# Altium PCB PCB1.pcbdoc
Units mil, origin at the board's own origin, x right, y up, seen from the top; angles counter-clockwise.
Board outline 1815 x 1125 mil, 2 copper layers (Top Layer, Bottom Layer); 37 components, 25 nets, 96 pads, 7 vias.
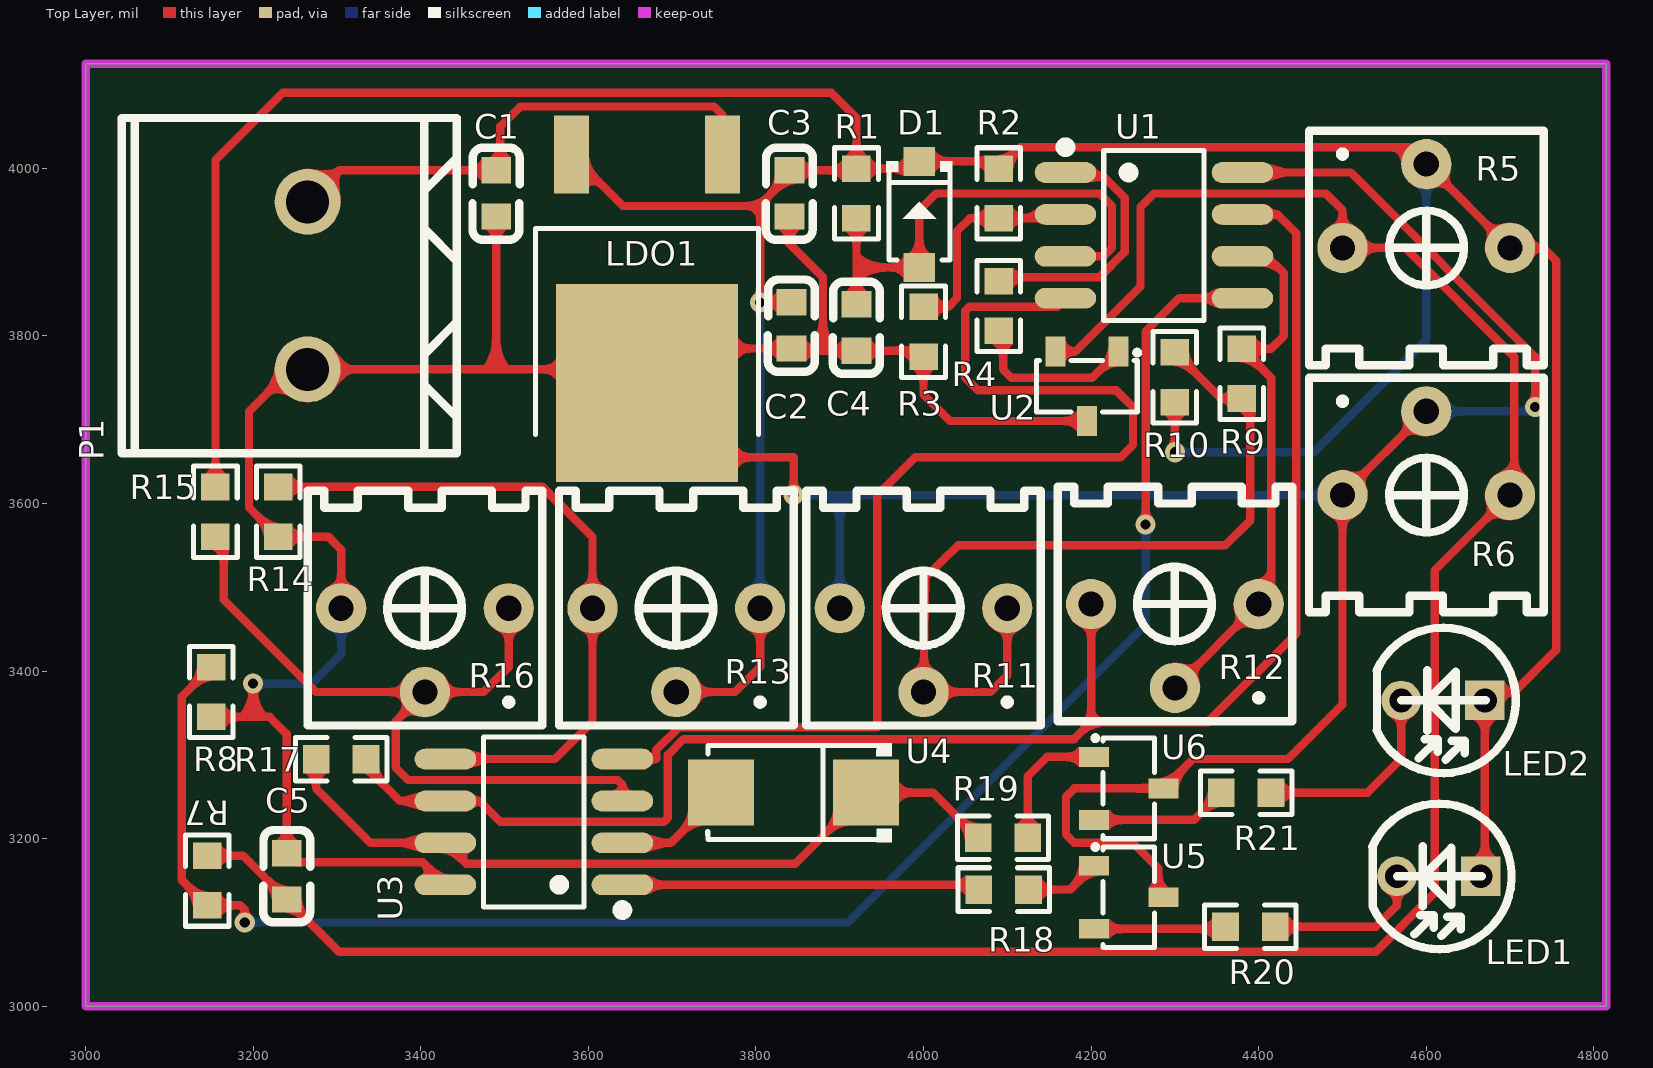
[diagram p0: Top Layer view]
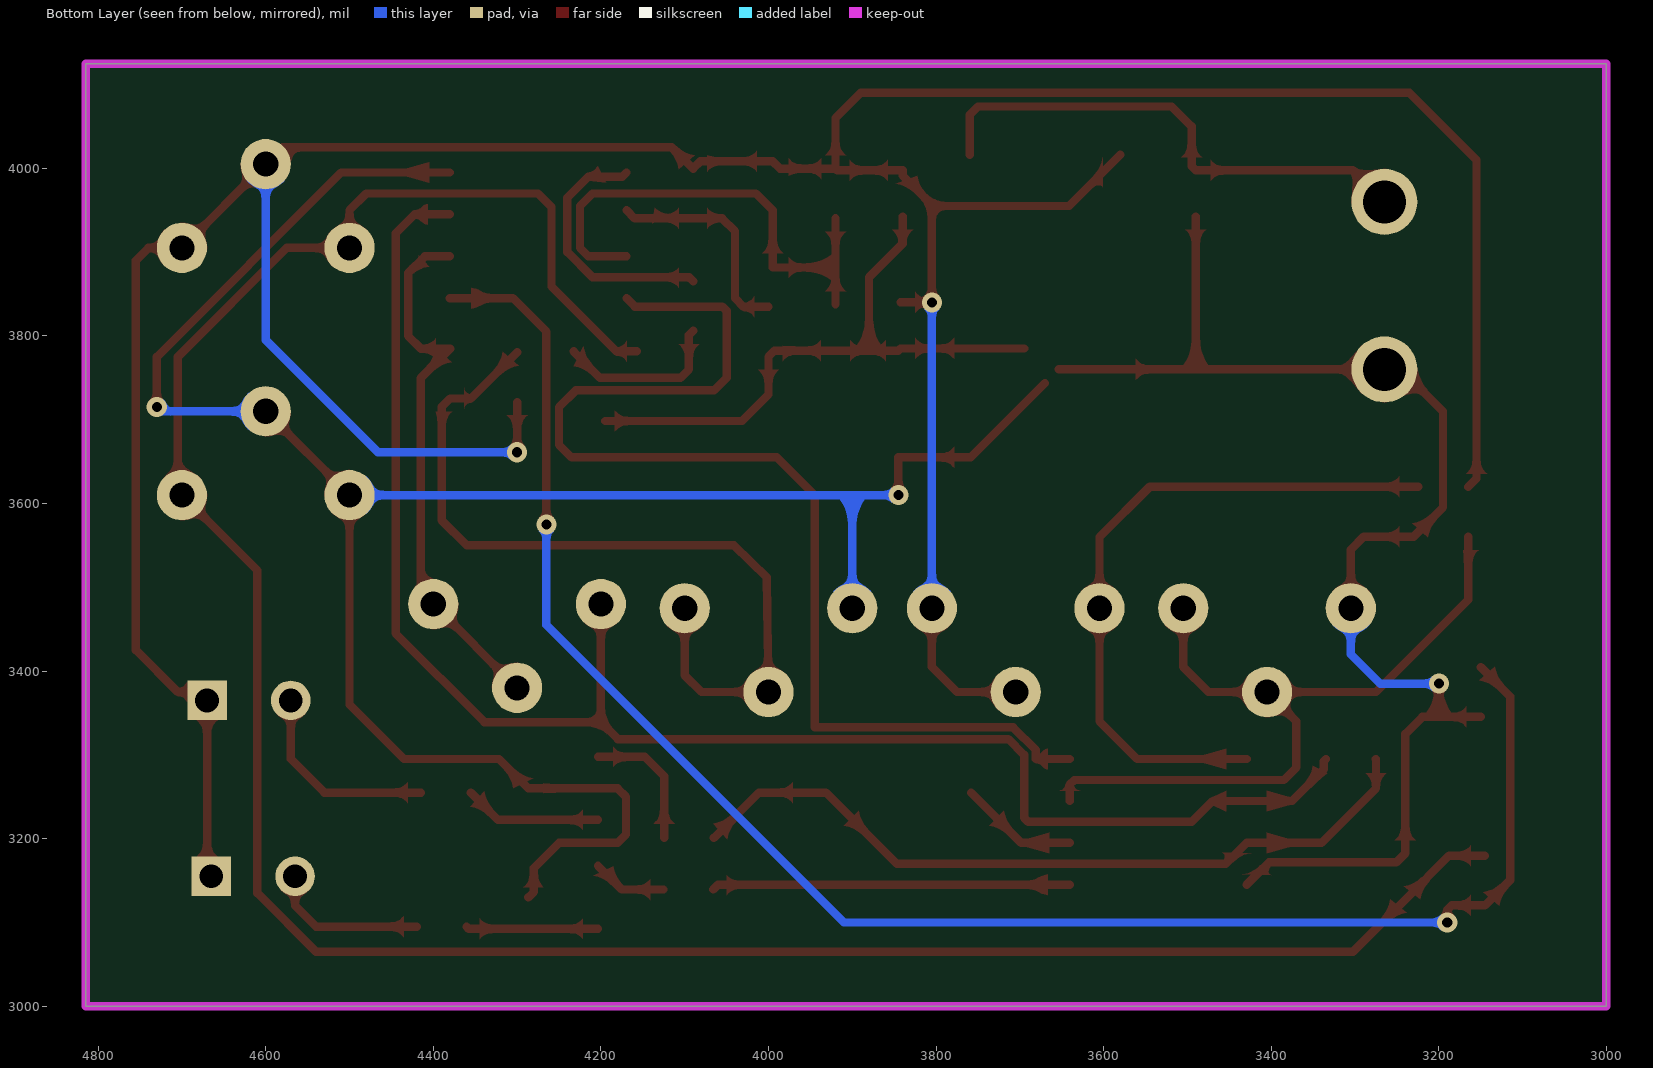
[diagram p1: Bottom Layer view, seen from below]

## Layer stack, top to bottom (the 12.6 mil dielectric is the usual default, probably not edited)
Top Layer: signal copper (thickness not stored)
Dielectric: dielectric 12.6, FR-4, Dk 4.8
Bottom Layer: signal copper (thickness not stored)

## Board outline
3000,3000 4815,3000 4815,4125 3000,4125

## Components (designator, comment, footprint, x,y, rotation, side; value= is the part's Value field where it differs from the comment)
C1 "CAP_0603" C0603 3490,3970 r90 top
C2 "CAP_0603" C0603 3842.44,3812.56 r90 top
C3 "CAP_0603" C0603 3840,3970 r90 top
C4 "CAP_0603" C0603 3920,3810 r90 top
C5 "CAP_0603" C0603 3240,3155 r270 top
D1 "1N4148W_C7420318" SOD-123_L2.7-W1.6-LS3.7-FD 3995,3945 r90 top
LDO1 "CJ7805 3%" TO-252-2_L6.6-W6.1-P4.58-LS10.1-BR-CW 3670,3880 r90 top
LED1 "PD204-6B" LED-TH_BD3.1-P2.54-FD 4615,3155 r180 top
LED2 "PD204-6B" LED-TH_BD3.1-P2.54-FD 4620,3365 r180 top
P1 "WJ500V-5.08-2P" CONN-TH_2P-P5.00_WJ500V-5.08-2P 3265,3860 r90 top
R1 "0603WAF1002T5E" R0603 3920,3970 r90 top
R2 "Res_0603" R0603 4090,3970 r90 top
R3 "Res_0603" R0603 4000,3805 r90 top
R4 "Res_0603" R0603 4090,3835.68 r270 top
R5 "3362P-1-103" RES-ADJ-TH_3362P 4600,3955 r0 top
R6 "3362P-1-103" RES-ADJ-TH_3362P 4600,3660 r0 top
R7 "Res_0603" R0603 3145,3150 r90 top
R8 "Res_0603" R0603 3150,3375 r90 top
R9 "Res_0603" R0603 4380,3755 r90 top
R10 "Res_0603" R0603 4300,3750.68 r270 top
R11 "3362P-1-103" RES-ADJ-TH_3362P 4000,3425 r180 top
R12 "3362P-1-103" RES-ADJ-TH_3362P 4300,3430 r180 top
R13 "3362P-1-103" RES-ADJ-TH_3362P 3705,3425 r180 top
R14 "Res_0603" R0603 3230,3590 r90 top
R15 "Res_0603" R0603 3155,3590 r90 top
R16 "3362P-1-103" RES-ADJ-TH_3362P 3405,3425 r180 top
R17 "Res_0603" R0603 3305,3295 r0 top
R18 "Res_0603" R0603 4095.59,3139.27 r180 top
R19 "Res_0603" R0603 4094.91,3201.03 r0 top
R20 "Res_0603" R0603 4390,3095 r180 top
R21 "Res_0603" R0603 4385,3255 r180 top
U1 "LM358_C5252902" SOP-8_L4.9-W3.9-P1.27-LS6.0-BL 4275,3920 r270 top
U2 "S9012_C5204710" SOT-23-3_L2.9-W1.4-P1.90-LS2.6-BR 4195,3740 r90 top
U3 "LM358_C5252902" SOP-8_L4.9-W3.9-P1.27-LS6.0-BL 3535,3220 r90 top
U4 "1N4007" SMA_L4.3-W2.6-LS5.1-RD 3845,3255 r180 top
U5 "S9012_C5204710" SOT-23-3_L2.9-W1.4-P1.90-LS2.6-BR 4245,3130 r180 top
U6 "S9012_C5204710" SOT-23-3_L2.9-W1.4-P1.90-LS2.6-BR 4245,3260 r180 top

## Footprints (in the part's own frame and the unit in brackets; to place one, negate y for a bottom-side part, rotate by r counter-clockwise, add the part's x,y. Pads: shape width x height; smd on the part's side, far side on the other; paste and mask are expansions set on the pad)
C0603 [mm]
  rect 0.8x0.9 smd: 1(-0.7,0) 2(0.7,0)
  silkscreen extent -1.41,-0.71 1.39,0.72
CONN-TH_2P-P5.00_WJ500V-5.08-2P [mm]
  round 2 hole 1.3: 1(-2.54,0) 2(2.54,0)
  silkscreen extent -5.08,-4.52 5.08,5.64
LED-TH_BD3.1-P2.54-FD [mm]
  rect 1.2x1.2 hole 0.72: 1(-1.27,0)
  round 1.2 hole 0.72: 2(1.27,0)
  silkscreen extent -2.2,-2.21 2.02,2.21
R0603 [mil]
  rect 31.75x34.02 smd: 1(-29.66,0) 2(29.66,0)
  silkscreen extent -55,-26 55,26
RES-ADJ-TH_3362P [mil]
  round 60 hole 30: 1(-100,-50) 2(0,50) 3(100,-50)
  silkscreen extent -140,-190 140,90
SMA_L4.3-W2.6-LS5.1-RD [mm]
  rect 2x2 smd: 1(-2.2,0) 2(2.2,0)
  silkscreen extent -2.98,-1.5 2.6,1.5
SOD-123_L2.7-W1.6-LS3.7-FD [mm]
  rect 0.88x0.96 smd: 1(-1.61,0) 2(1.61,0)
  silkscreen extent -1.38,-1 1.6,1
SOP-8_L4.9-W3.9-P1.27-LS6.0-BL [mm]
  oval 0.63x1.865 smd: 1(-1.905,-2.682) 2(-0.635,-2.682) 3(0.635,-2.682) 4(1.905,-2.682) 5(1.905,2.682) 6(0.635,2.682) 7(-0.635,2.682) 8(-1.905,2.682)
  silkscreen extent -2.82,-2.83 2.58,1.52
SOT-23-3_L2.9-W1.4-P1.90-LS2.6-BR [mm]
  rect 0.91x0.6 smd: 1(1.055,-0.955) 2(1.055,0.955) 3(-1.055,0)
  silkscreen extent -0.78,-1.6 1.09,1.53
TO-252-2_L6.6-W6.1-P4.58-LS10.1-BR-CW [mil]
  rect 93.07x41.89 smd: 1(136.3,-90) 3(136.3,90)
  rect 236.37x217.01 smd: 2(-136.3,0)
  silkscreen extent -198,-133 48,133

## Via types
v1: diameter 24.02, hole 12.01, Top Layer to Bottom Layer, 7 vias

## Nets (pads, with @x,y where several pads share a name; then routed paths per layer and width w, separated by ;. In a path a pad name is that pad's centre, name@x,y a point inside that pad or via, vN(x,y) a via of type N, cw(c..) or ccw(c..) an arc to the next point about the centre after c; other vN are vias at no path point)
$1N1076: C1.2 LDO1.1 P1.2 | length 621.6
  Top Layer w10: P1.2 3302.56,3997.56 C1.2 3495,4002.56 3495,4050 3518.83,4073.83 3750,4073.83 3760,4063.83 LDO1.1
$1N1870: C4.2 D1.1 R1.1 U1.3 | length 600.8
  Top Layer w10: C4.2 3920,3880.72 ; R1.1 3920,3880.72 ; U1.3 4215,3895 4225,3905 4225,3955 4210,3970 4015,3970 3995,3950 D1.1 3920.89,3881.61 3920,3880.72
$1N2082: R2.1 R3.2 U1.2 | length 264
  Top Layer w10: R3.2 4029.66,3834.66 4040,3845 4040,3925 4055.34,3940.34 R2.1 4159.73,3940.34 U1.2@4169.39,3950
$1N2247: R4.1 U1.1 | length 312.4
  Top Layer w10: R4.1 4094.66,3870 4210,3870 4240,3900 4240,3965 4215,3990 4174.39,3990 U1.1
$1N2341: R4.2 U2.1 | length 202.9
  Top Layer w10: R4.2 4095,3801.02 4095,3760 4105,3750 4201.06,3750 U2.1
$1N2823: C5.2 R5.1 R6.3 R7.2 U2.2 | length 3009.3
  Top Layer w10: R7.2 3187.78,3179.66 C5.2 3302.44,3065 4540,3065 4610,3135 4610,3520 R6.3 4705,3615 4705,3775 4575,3905 R5.1 4500,3950 4480,3970 4275,3970 4258.98,3953.98 4258.98,3858.98 4181.54,3781.54 U2.2
$1N2886: R7.1 R8.2 U1.5 | length 2077.7
  Top Layer w10: R8.2 3115,3369.66 3115,3150.34 R7.1 3184.66,3120.34 3190,3115 v1(3190,3100) ; v1(4265,3575) 4265,3805 4305,3845 U1.5
  Bottom Layer w10: v1(3190,3100) 3910,3100 4265,3455 v1(4265,3575)
$1N3156: R9.1 R10.1 R11.1 R11.2 | length 993.4
  Top Layer w10: R11.1 4100,3395 4080,3375 R11.2 4001.93,3511.87 4041.14,3550 4360,3550 4390,3580 4390,3715.34 R9.1 4355,3725.34 R10.1
$1N3303: R9.2 R12.1 R12.2 U1.6 | length 663.9
  Top Layer w10: R12.2 R12.1 ; U1.6 4410,3895 4430,3875 4430,3800 4414.66,3784.66 R9.2 4415,3749.66 4415,3505 R12.1@4407.69,3497.69 ; R12.1@4407.69,3497.69 4405.38,3500 4400,3500 4400.26,3499.74 4400.26,3490.26 R12.1@4407.69,3497.69
$1N4357: U3.2 U4.2 | length 142.6
  Top Layer w10: U3.2 3698.39,3195 U4.2
$1N4404: R15.1 R16.1 R16.2 U3.3 | length 946.4
  Top Layer w10: R15.1@3165,3560.34 3165,3485 3275,3375 R16.2 ; R16.1 3505,3405 3475,3375 R16.2 ; U3.3 3640.61,3264.39 3635,3270 3385,3270 3370,3285 3370,3340 R16.2
$1N4441: R13.3 R14.2 U3.5 | length 819.4
  Top Layer w10: R14.2@3224.66,3620 3545,3620 3605,3560 R13.3 3605,3340 3560,3295 U3.5
$1N4449: R12.3 R17.2 U1.7 U3.6 | length 1986.3
  Top Layer w10: R17.2 3337.33,3292.33 3337.33,3282.67 3375,3245 U3.6 3470,3245 3495,3220 3690,3220 3695,3225 3695,3300 3713.78,3318.78 4179.78,3318.78 4200,3339 ; R12.3@4200,3490 4200,3339 ; U1.7 4422.32,3945 4445,3922.32 4445,3445 4339,3339 4200,3339
$1N4581: R18.2 U3.1 | length 427.7
  Top Layer w10: U3.1 4060.2,3145 R18.2
$1N4611: R17.1 R19.1 U3.7 U4.1 | length 920.2
  Top Layer w10: R17.1 3275,3294.66 3275,3260 3340,3195 U3.7 3454.39,3170 3846.62,3170 U4.1 4011.29,3255 R19.1
$1N4719: R18.1 U5.1 | length 89.9
  Top Layer w10: R18.1 4175.13,3139.27 U5.1
$1N4722: R19.2 U6.1 | length 162
  Top Layer w10: R19.2 4124.57,3274.57 4147.6,3297.6 U6.1
$1N4773: R21.2 U6.2 | length 165.4
  Top Layer w10: U6.2 4322.74,3222.4 R21.2
$1N4777: R20.2 U5.2 | length 158
  Top Layer w10: U5.2 4357.74,3092.4 R20.2
$1N4889: LED2.2 R21.1 | length 241.9
  Top Layer w10: R21.1 4530,3255 4570,3295 LED2.2
$1N4892: LED1.2 R20.1 | length 190.7
  Top Layer w10: R20.1 4540,3095 4565,3120 LED1.2
$1N5001: C2.2 C3.2 D1.2 LDO1.3 LED1.1 LED2.1 R1.2 R2.2 R5.2 R5.3 R10.2 R13.1 R13.2 R15.2 | length 4665.4
  Top Layer w10: R15.2@3165,3619.66 3155,3629.66 3155,4010 3235,4090 3890,4090 3920,4060 R1.2 ; LDO1.3 3641.3,3955 3803.54,3955 ; R13.2 3775,3375 3805,3405 R13.1 ; C2.2 3842.32,3840 v1(3805,3840) 3805,3953.54 3803.54,3955 ; v1@4300,3670 R10.2 ; LED1.1 4670,3160 LED2.1 4680,3375 4705,3375 4755,3425 4755,3890 4740,3905 R5.3 R5.2 4580,4025 4115.34,4025 R2.2 4081.27,4008.39 D1.2 3986.27,3999.66 R1.2 ; 3803.54,3955 3840,3991.46 C3.2 3917.9,3997.56 R1.2
  Bottom Layer w10: R13.1 v1(3805,3840) ; v1(4300,3661.12) 4466.12,3661.12 4600,3795 R5.2
+9V: U1.4 U3.4 | length 1398.5
  Top Layer w10: U3.4 3680.98,3295 3680.98,3305.81 3707.97,3332.79 3945,3332.79 3945,3610 3990,3655 4235,3655 4250,3670 4250,3715 4230,3735 4065,3735 4050,3750 4050,3830 4055,3835 4159.39,3835 U1.4
GND: C1.1 C2.1 C3.1 C4.1 C5.1 LDO1.2 P1.1 R3.1 R6.1 R6.2 R8.1 R11.3 R14.1 R16.3 U1.8 U2.3 U3.8 U5.3 U6.3 | length 5032.5
  Top Layer w10: R8.1 3200,3345.34 ; v1(3200,3385) 3200,3345.34 ; R16.3 3305,3545 3289.66,3560.34 R14.1 3195,3595.34 3195,3710 3245,3760 P1.1 3490,3760 ; U3.8 3402.67,3171.72 3250.84,3171.72 C5.1 3240,3325 3219.66,3345.34 3200,3345.34 ; C1.1 3490,3760 ; LDO1.2@3653.7,3760 3490,3760 ; LDO1.2 3758.7,3655 3845,3655 v1(3845,3610) ; LDO1.2@3695,3785 C2.1 3845,3782.44 3881.17,3782.44 ; C3.1 3840,3910 3880,3870 3880,3783.61 3881.17,3782.44 ; U2.3 4031.54,3698.46 4000,3730 R3.1 3992.9,3782.44 C4.1 3881.17,3782.44 ; U5.3 4280,3136.54 4280,3165 4250,3195 4180,3195 4170,3205 4170,3250 4180,3260 U6.3 4321.54,3295 4435,3295 4500,3360 R6.1 R6.2 ; U1.8 4510,3995 4730,3775 v1(4730,3715)
  Bottom Layer w10: v1(3200,3385) 3270,3385 3305,3420 R16.3 ; v1(3845,3610) 3900.23,3610 ; R11.3 3900,3609.77 3900.23,3610 ; R6.1 3900.23,3610 ; R6.2 4725,3710 v1(4730,3715)
"": 

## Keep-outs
Board Outline Layer:
  the board outline again, w10

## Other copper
Top Layer:
  drawing of 140 lines, arcs and shapes, not listed
Bottom Layer:
  region net $1N5001: 4595,3964.16 4605,3964.16 4605.06,3965.92 4605.16,3966.99 4605.3,3967.98 4605.49,3968.9 4605.73,3969.75 4606.01,3970.54 4606.33,3971.28 4606.69,3971.96 4607.08,3972.59 4607.52,3973.18 4607.98,3973.73 4608.48,3974.26 4609.01,3974.75 4609.87,3975.45 4611.1,3976.33 4615.31,3979.04 4617.24,3980.38 4618.83,3981.61 4620.05,3982.66 4621.27,3983.84 4622.5,3985.16 4577.5,3985.16 4578.73,3983.84 4579.95,3982.66 4581.57,3981.29 4583.15,3980.09 4585.8,3978.32 4589.22,3976.12 4590.13,3975.45 4590.99,3974.75 4591.52,3974.26 4592.02,3973.73 4592.48,3973.18 4592.92,3972.59 4593.31,3971.96 4593.67,3971.28 4593.99,3970.54 4594.27,3969.75 4594.51,3968.9 4594.7,3967.98 4594.84,3966.99 4594.94,3965.92
  region net GND: 4640.84,3705 4640.84,3715 4639.08,3715.06 4638.01,3715.16 4637.02,3715.3 4636.1,3715.49 4635.25,3715.73 4634.46,3716.01 4633.72,3716.33 4633.04,3716.69 4632.41,3717.08 4631.82,3717.52 4631.27,3717.98 4630.74,3718.48 4630.25,3719.01 4629.55,3719.87 4628.67,3721.1 4625.96,3725.31 4624.62,3727.24 4623.39,3728.83 4622.34,3730.05 4621.16,3731.27 4619.84,3732.5 4619.84,3687.5 4621.16,3688.73 4622.34,3689.95 4623.71,3691.57 4624.91,3693.15 4626.68,3695.8 4628.88,3699.22 4629.55,3700.13 4630.25,3700.99 4630.74,3701.52 4631.27,3702.02 4631.82,3702.48 4632.41,3702.92 4633.04,3703.31 4633.72,3703.67 4634.46,3703.99 4635.25,3704.27 4636.1,3704.51 4637.02,3704.7 4638.01,3704.84 4639.08,3704.94
  region net GND: 4459.16,3615 4459.16,3605 4460.92,3604.94 4461.99,3604.84 4462.98,3604.7 4463.9,3604.51 4464.75,3604.27 4465.54,3603.99 4466.28,3603.67 4466.96,3603.31 4467.59,3602.92 4468.18,3602.48 4468.73,3602.02 4469.26,3601.52 4469.75,3600.99 4470.45,3600.13 4471.33,3598.9 4474.04,3594.69 4475.38,3592.76 4476.61,3591.17 4477.66,3589.95 4478.84,3588.73 4480.16,3587.5 4480.16,3632.5 4478.84,3631.27 4477.66,3630.05 4476.29,3628.43 4475.09,3626.85 4473.32,3624.2 4471.12,3620.78 4470.45,3619.87 4469.75,3619.01 4469.26,3618.48 4468.73,3617.98 4468.18,3617.52 4467.59,3617.08 4466.96,3616.69 4466.28,3616.33 4465.54,3616.01 4464.75,3615.73 4463.9,3615.49 4462.98,3615.3 4461.99,3615.16 4460.92,3615.06
  region net GND: 3905,3515.84 3895,3515.84 3894.94,3514.08 3894.84,3513.01 3894.7,3512.02 3894.51,3511.1 3894.27,3510.25 3893.99,3509.46 3893.67,3508.72 3893.31,3508.04 3892.92,3507.41 3892.48,3506.82 3892.02,3506.27 3891.52,3505.74 3890.99,3505.25 3890.13,3504.55 3888.9,3503.67 3884.69,3500.96 3882.76,3499.62 3881.17,3498.39 3879.95,3497.34 3878.73,3496.16 3877.5,3494.84 3922.5,3494.84 3921.27,3496.16 3920.05,3497.34 3918.43,3498.71 3916.85,3499.91 3914.2,3501.68 3910.78,3503.88 3909.87,3504.55 3909.01,3505.25 3908.48,3505.74 3907.98,3506.27 3907.52,3506.82 3907.08,3507.41 3906.69,3508.04 3906.33,3508.72 3906.01,3509.46 3905.73,3510.25 3905.49,3511.1 3905.3,3512.02 3905.16,3513.01 3905.06,3514.08
  region net $1N5001: 3810,3515.84 3800,3515.84 3799.94,3514.08 3799.84,3513.01 3799.7,3512.02 3799.51,3511.1 3799.27,3510.25 3798.99,3509.46 3798.67,3508.72 3798.31,3508.04 3797.92,3507.41 3797.48,3506.82 3797.02,3506.27 3796.52,3505.74 3795.99,3505.25 3795.13,3504.55 3793.9,3503.67 3789.69,3500.96 3787.76,3499.62 3786.17,3498.39 3784.95,3497.34 3783.73,3496.16 3782.5,3494.84 3827.5,3494.84 3826.27,3496.16 3825.05,3497.34 3823.43,3498.71 3821.85,3499.91 3819.2,3501.68 3815.78,3503.88 3814.87,3504.55 3814.01,3505.25 3813.48,3505.74 3812.98,3506.27 3812.52,3506.82 3812.08,3507.41 3811.69,3508.04 3811.33,3508.72 3811.01,3509.46 3810.73,3510.25 3810.49,3511.1 3810.3,3512.02 3810.16,3513.01 3810.06,3514.08
  region net GND: 3300,3434.16 3310,3434.16 3310.06,3435.92 3310.16,3436.99 3310.3,3437.98 3310.49,3438.9 3310.73,3439.75 3311.01,3440.54 3311.33,3441.28 3311.69,3441.96 3312.08,3442.59 3312.52,3443.18 3312.98,3443.73 3313.48,3444.26 3314.01,3444.75 3314.87,3445.45 3316.1,3446.33 3320.31,3449.04 3322.24,3450.38 3323.83,3451.61 3325.05,3452.66 3326.27,3453.84 3327.5,3455.16 3282.5,3455.16 3283.73,3453.84 3284.95,3452.66 3286.57,3451.29 3288.15,3450.09 3290.8,3448.32 3294.22,3446.12 3295.13,3445.45 3295.99,3444.75 3296.52,3444.26 3297.02,3443.73 3297.48,3443.18 3297.92,3442.59 3298.31,3441.96 3298.67,3441.28 3298.99,3440.54 3299.27,3439.75 3299.51,3438.9 3299.7,3437.98 3299.84,3436.99 3299.94,3435.92
  region net GND: 3861.35,3605 3861.35,3615 3860.78,3615.02 3860.21,3615.09 3859.64,3615.2 3859.08,3615.34 3858.51,3615.53 3857.41,3615.98 3856.33,3616.54 3855.29,3617.19 3854.3,3617.89 3852.94,3619.01 3852.94,3600.99 3854.3,3602.11 3855.29,3602.81 3856.33,3603.46 3857.41,3604.02 3858.51,3604.47 3859.08,3604.66 3859.64,3604.8 3860.21,3604.91 3860.78,3604.98
  region net GND: 3216.35,3380 3216.35,3390 3215.78,3390.02 3215.21,3390.09 3214.64,3390.2 3214.08,3390.34 3213.51,3390.53 3212.41,3390.98 3211.33,3391.54 3210.29,3392.19 3209.3,3392.89 3207.94,3394.01 3207.94,3375.99 3209.3,3377.11 3210.29,3377.81 3211.33,3378.46 3212.41,3379.02 3213.51,3379.47 3214.08,3379.66 3214.64,3379.8 3215.21,3379.91 3215.78,3379.98
  region net $1N5001: 3800,3823.65 3810,3823.65 3810.02,3824.22 3810.09,3824.79 3810.2,3825.36 3810.34,3825.92 3810.53,3826.49 3810.98,3827.59 3811.54,3828.67 3812.19,3829.71 3812.89,3830.7 3814.01,3832.06 3795.99,3832.06 3797.11,3830.7 3797.81,3829.71 3798.46,3828.67 3799.02,3827.59 3799.47,3826.49 3799.66,3825.92 3799.8,3825.36 3799.91,3824.79 3799.98,3824.22
  region net $1N2886: 4260,3558.65 4270,3558.65 4270.02,3559.22 4270.09,3559.79 4270.2,3560.36 4270.34,3560.92 4270.53,3561.49 4270.98,3562.59 4271.54,3563.67 4272.19,3564.71 4272.89,3565.7 4274.01,3567.06 4255.99,3567.06 4257.11,3565.7 4257.81,3564.71 4258.46,3563.67 4259.02,3562.59 4259.47,3561.49 4259.66,3560.92 4259.8,3560.36 4259.91,3559.79 4259.98,3559.22
  region net $1N2886: 3206.35,3095 3206.35,3105 3205.78,3105.02 3205.21,3105.09 3204.64,3105.2 3204.08,3105.34 3203.51,3105.53 3202.41,3105.98 3201.33,3106.54 3200.29,3107.19 3199.3,3107.89 3197.94,3109.01 3197.94,3090.99 3199.3,3092.11 3200.29,3092.81 3201.33,3093.46 3202.41,3094.02 3203.51,3094.47 3204.08,3094.66 3204.64,3094.8 3205.21,3094.91 3205.78,3094.98
  region net $1N5001: 4316.35,3656.12 4316.35,3666.12 4315.78,3666.14 4315.21,3666.21 4314.64,3666.32 4314.08,3666.46 4313.51,3666.65 4312.41,3667.1 4311.33,3667.66 4310.29,3668.31 4309.3,3669.01 4307.94,3670.13 4307.94,3652.11 4309.3,3653.23 4310.29,3653.93 4311.33,3654.58 4312.41,3655.14 4313.51,3655.59 4314.08,3655.78 4314.64,3655.92 4315.21,3656.03 4315.78,3656.1
  region net GND: 4713.65,3715 4713.65,3705 4714.62,3705.11 4715.72,3705.38 4718.08,3706.09 4719.24,3706.37 4720.33,3706.5 4721.28,3706.4 4722.06,3705.99 4722.06,3724.01 4721.58,3723.53 4721.1,3722.97 4720.15,3721.65 4718.17,3718.66 4717.13,3717.26 4716.6,3716.64 4716.04,3716.09 4715.47,3715.64 4714.89,3715.29 4714.28,3715.08
  region net GND: 3905,3575 3895,3575 ccw(c3845,3575) 3885,3605 3915,3605 ccw(c3955,3575)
